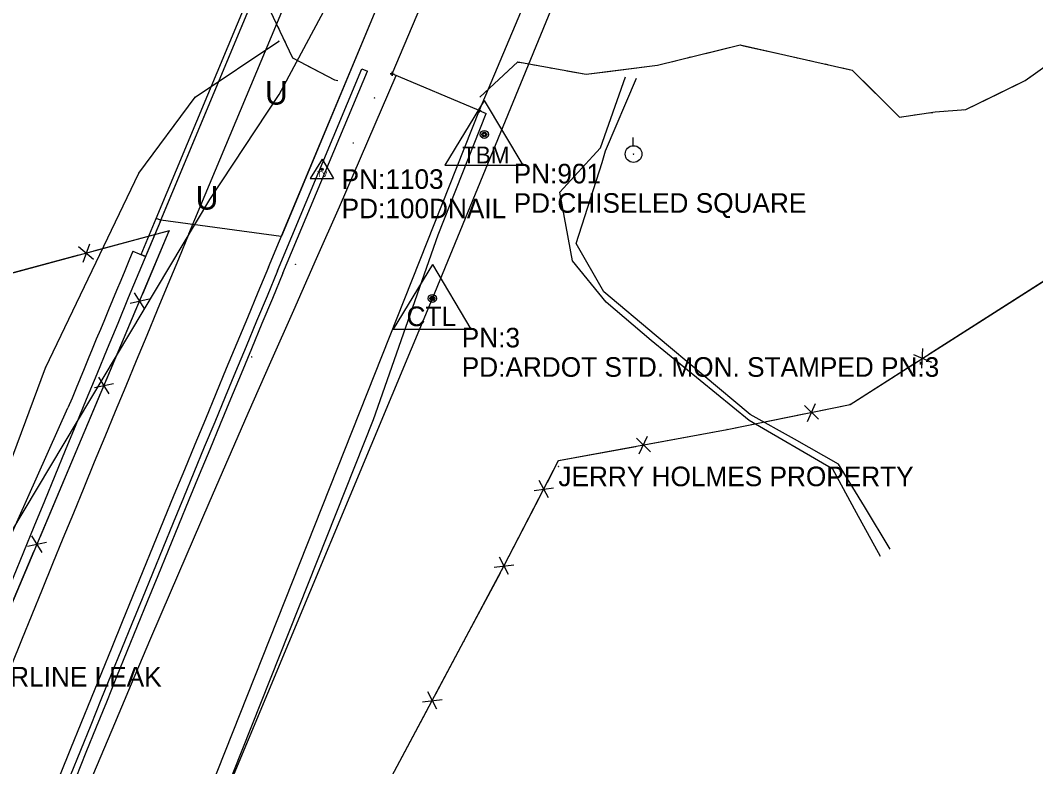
# Model space of a CAD drawing. Extents: x 1282810 to 1284464, y 402460 to 405899.
# Drawn here: x 1283291.6 to 1283550.7, y 403680.6 to 403871.1 of the extents above; entities that cross this region are included whole.
import ezdxf

# ---------------------------------------------------------------- set-up
doc = ezdxf.new("R2010")
doc.units = 0
for name, color, linetype in [('Default', 7, 'Continuous'), ('MOT_Bridge_Stage 2', 7, 'Continuous'), ('MOT_Proposed Road_Stage 2', 7, 'Continuous'), ('MOT_Shld_Stage 2', 7, 'Continuous'), ('MOT_Stage 1_Proposed Road', 7, 'Continuous'), ('MOT_Stage 1_Shld', 7, 'Continuous'), ('MOT_Stage 2_Retaining Wall', 7, 'Continuous'), ('S_BASELINE', 7, 'Continuous'), ('S_BRIDGE', 7, 'Continuous'), ('S_DITCHLINE', 7, 'Continuous'), ('S_EDGE_PAVEMENT', 7, 'Continuous'), ('S_FENCE', 7, 'Continuous'), ('S_MSC_PT_SYM', 7, 'Continuous'), ('S_PRIMARY_CTL', 7, 'Continuous'), ('S_PRIMARY_CTL_ANNOT', 7, 'Continuous'), ('S_RDW_PT_SYM', 7, 'Continuous'), ('S_SECONDARY_CTL', 7, 'Continuous'), ('S_SECONDARY_CTL_ANNOT', 7, 'Continuous'), ('S_STR_PT_SYM', 7, 'Continuous'), ('S_STREAM', 7, 'Continuous'), ('S_SURVEY_TEXT_ANNOT', 7, 'Continuous'), ('S_UNDERGROUND_CABLE', 7, 'Continuous'), ('S_UTILITY_POLE', 7, 'Continuous'), ('S_UTL_PT_SYM', 7, 'Continuous'), ('S_WATER_UTILITIES', 7, 'Continuous')]:
    doc.layers.add(name, color=color, linetype=linetype)

msp = doc.modelspace()

# ---------------------------------------------------------------- linework, layer by layer
at = {"layer": 'MOT_Bridge_Stage 2'}
for p, q in [((1283326.31, 403820.53), (1283390.08, 403973.25)), ((1283327.46, 403820.05), (1283391.24, 403972.77)), ((1283358.34, 403816.13), (1283421.92, 403968.39)), ((1283322.45, 403811.3), (1283326.31, 403820.53)), ((1283327.46, 403820.05), (1283323.61, 403810.82)), ((1283327.46, 403820.05), (1283326.31, 403820.53)), ((1283327.46, 403820.05), (1283326.31, 403820.53)), ((1283358.24, 403815.9), (1283327.46, 403820.05)), ((1283323.61, 403810.82), (1283322.45, 403811.3))]:
    msp.add_line(p, q, dxfattribs=at)
at = {"layer": 'MOT_Proposed Road_Stage 2'}
for p, q in [((1283334.68, 403816.57), (1283508.7, 404233.27)), ((1283354.98, 403808.09), (1283529, 404224.79))]:
    msp.add_line(p, q, dxfattribs=at)
for radius in [11483.16, 11461.16]:
    msp.add_arc((1293930.9, 399391.32), radius, 157.333333, 159.572534, dxfattribs=at)
at = {"layer": 'MOT_Shld_Stage 2'}
for p, q in [((1283327.3, 403819.65), (1283501.32, 404236.35)), ((1283327.3, 403819.65), (1283501.32, 404236.35)), ((1283327.3, 403819.65), (1283501.32, 404236.35)), ((1283327.3, 403819.65), (1283501.32, 404236.35)), ((1283327.3, 403819.65), (1283501.32, 404236.35)), ((1283327.3, 403819.65), (1283501.32, 404236.35)), ((1283320.38, 403812.17), (1283323.61, 403810.82)), ((1283262.75, 403680.57), (1283303.81, 403772.18))]:
    msp.add_line(p, q, dxfattribs=at)
for centre, radius, start, end in [((1293930.9, 399391.32), 11491.16, 157.333333, 159.572534), ((1293930.9, 399391.32), 11491.16, 157.333333, 159.572534), ((1293931.6, 399392.99), 11494.66, 157.390099, 157.605879)]:
    msp.add_arc(centre, radius, start, end, dxfattribs=at)
at = {"layer": 'MOT_Stage 1_Proposed Road'}
msp.add_line((1283408.71, 403848.09), (1283219.41, 403370.59), dxfattribs=at)
at = {"layer": 'MOT_Stage 1_Shld'}
for p in [(1283408.71, 403848.09), (1283398.29, 403816.37)]:
    msp.add_line(p, (1283410.55, 403847.31), dxfattribs=at)
msp.add_lwpolyline([(1283335.29, 403647.86), (1283341.21, 403666.97), (1283381.73, 403769.19), (1283398.29, 403816.37)], dxfattribs=at)
at = {"layer": 'MOT_Stage 2_Retaining Wall'}
for p, q in [((1283357.29, 403807.13), (1283378.82, 403858.69)), ((1283358.67, 403806.55), (1283380.2, 403858.12)), ((1283378.82, 403858.69), (1283380.2, 403858.12))]:
    msp.add_line(p, q, dxfattribs=at)
for radius in [11458.66, 11457.16]:
    msp.add_arc((1293930.9, 399391.32), radius, 157.333333, 159.562079, dxfattribs=at)
at = {"layer": 'S_BASELINE'}
for p, q in [((1283396.79, 403800.11), (1283700.58, 404538.68)), ((1283161.19, 403235.09), (1283396.79, 403800.11))]:
    msp.add_line(p, q, dxfattribs=at)
at = {"layer": 'S_BRIDGE'}
for p, q in [((1283386.52, 403857.44), (1283422.73, 403943.16)), ((1283444.84, 403934.02), (1283408.77, 403848.06)), ((1283408.77, 403848.06), (1283386.52, 403857.44))]:
    msp.add_line(p, q, dxfattribs=at)
at = {"layer": 'S_DITCHLINE'}
for points in [[(1283511.1, 403734.2), (1283505.03, 403745.35), (1283498.95, 403756.51), (1283477.63, 403768.95), (1283465.12, 403779.18), (1283452.62, 403789.41), (1283441.17, 403799.2), (1283432.51, 403809.71), (1283429.32, 403827.22), (1283437.77, 403836.44), (1283439.67, 403838.54), (1283446.03, 403856.66)], [(1283513.65, 403736.12), (1283507.05, 403746.98), (1283500.44, 403757.84), (1283489.17, 403764.16), (1283477.9, 403770.48), (1283465.9, 403780.51), (1283453.89, 403790.55), (1283440.57, 403801.81), (1283433.46, 403814.15), (1283440.11, 403834.82), (1283440.95, 403837.76), (1283448.85, 403856.35)]]:
    msp.add_lwpolyline(points, dxfattribs=at)
at = {"layer": 'S_EDGE_PAVEMENT'}
msp.add_lwpolyline([(1283293.23, 403639.37), (1283302.63, 403661.02), (1283310.16, 403678.33), (1283315.1, 403690.01), (1283320.05, 403701.69), (1283324.99, 403713.37), (1283329.94, 403725.05), (1283339.86, 403747.91), (1283349.79, 403770.78), (1283355.61, 403783.95), (1283361.42, 403797.12), (1283367.24, 403810.3), (1283373.06, 403823.47), (1283380.28, 403840.24), (1283387.51, 403857.01)], dxfattribs=at)
at = {"layer": 'S_FENCE'}
for p, q in [((1283329.66, 403817.36), (1283143.67, 403767.43)), ((1283261.12, 403654.99), (1283329.66, 403817.36)), ((1283309.27, 403814), (1283307.56, 403809.3)), ((1283503.36, 403773.04), (1283570.67, 403815.95)), ((1283310.33, 403810.05), (1283306.5, 403813.26)), ((1283323.44, 403797.34), (1283320.78, 403801.58)), ((1283319.66, 403798.94), (1283324.55, 403799.99)), ((1283519.53, 403785.77), (1283524.14, 403783.85)), ((1283521.73, 403782.32), (1283521.93, 403787.31)), ((1283310.55, 403777.36), (1283315.44, 403778.4)), ((1283314.33, 403775.76), (1283311.67, 403780)), ((1283471.99, 403766.62), (1283503.36, 403773.04)), ((1283491.72, 403772.75), (1283495.35, 403769.31)), ((1283492.54, 403768.73), (1283494.53, 403773.32)), ((1283429.01, 403758.73), (1283471.99, 403766.62)), ((1283449.6, 403760.43), (1283451.68, 403764.97)), ((1283448.86, 403764.46), (1283452.42, 403760.95)), ((1283415.11, 403731.9), (1283429.01, 403758.73)), ((1283422.75, 403751.09), (1283427.7, 403751.75)), ((1283426.39, 403749.21), (1283424.07, 403753.64)), ((1283297.22, 403735.24), (1283294.56, 403739.47)), ((1283293.44, 403736.83), (1283298.33, 403737.88)), ((1283416.21, 403729.6), (1283413.92, 403734.03)), ((1283404.86, 403712.59), (1283415.11, 403731.9)), ((1283412.59, 403731.52), (1283417.54, 403732.11)), ((1283386.47, 403678.17), (1283404.86, 403712.59)), ((1283394.29, 403697.15), (1283399.25, 403697.73)), ((1283397.9, 403695.22), (1283395.63, 403699.66))]:
    msp.add_line(p, q, dxfattribs=at)
for points in [[(1283329.66, 403817.36), (1283310.35, 403812.17)], [(1283322.89, 403801.3), (1283329.66, 403817.36)], [(1283306.48, 403811.13), (1283267.85, 403800.76)], [(1283523.51, 403785.88), (1283557.1, 403807.3)], [(1283313.55, 403779.2), (1283321.33, 403797.62)], [(1283503.36, 403773.04), (1283520.15, 403783.74)], [(1283296.67, 403739.2), (1283312.22, 403776.04)], [(1283495.49, 403771.43), (1283503.36, 403773.04)], [(1283471.99, 403766.62), (1283491.57, 403770.63)], [(1283452.6, 403763.06), (1283471.99, 403766.62)], [(1283429.01, 403758.73), (1283448.67, 403762.34)], [(1283426.15, 403753.2), (1283429.01, 403758.73)], [(1283415.11, 403731.9), (1283424.31, 403749.65)], [(1283287.34, 403717.1), (1283295.11, 403735.52)], [(1283404.86, 403712.59), (1283414.14, 403730.07)], [(1283397.71, 403699.19), (1283404.86, 403712.59)], [(1283386.47, 403678.17), (1283395.83, 403695.69)]]:
    msp.add_lwpolyline(points, dxfattribs=at)
at = {"layer": 'S_MSC_PT_SYM'}
for points in [[(1283329.66, 403817.36), (1283329.66, 403817.41), (1283329.66, 403817.36), (1283329.61, 403817.36), (1283329.66, 403817.36), (1283329.66, 403817.31), (1283329.66, 403817.36), (1283329.71, 403817.36)], [(1283503.36, 403773.04), (1283503.36, 403773.09), (1283503.36, 403773.04), (1283503.31, 403773.04), (1283503.36, 403773.04), (1283503.36, 403772.99), (1283503.36, 403773.04), (1283503.41, 403773.04)], [(1283471.99, 403766.62), (1283471.99, 403766.67), (1283471.99, 403766.62), (1283471.94, 403766.62), (1283471.99, 403766.62), (1283471.99, 403766.57), (1283471.99, 403766.62), (1283472.04, 403766.62)], [(1283428.95, 403757.18), (1283428.95, 403757.23), (1283428.95, 403757.18), (1283428.9, 403757.18), (1283428.95, 403757.18), (1283428.95, 403757.13), (1283428.95, 403757.18), (1283429, 403757.18)], [(1283429.01, 403758.73), (1283429.01, 403758.78), (1283429.01, 403758.73), (1283428.96, 403758.73), (1283429.01, 403758.73), (1283429.01, 403758.68), (1283429.01, 403758.73), (1283429.06, 403758.73)], [(1283415.11, 403731.9), (1283415.11, 403731.95), (1283415.11, 403731.9), (1283415.06, 403731.9), (1283415.11, 403731.9), (1283415.11, 403731.85), (1283415.11, 403731.9), (1283415.16, 403731.9)], [(1283404.86, 403712.59), (1283404.86, 403712.64), (1283404.86, 403712.59), (1283404.81, 403712.59), (1283404.86, 403712.59), (1283404.86, 403712.54), (1283404.86, 403712.59), (1283404.91, 403712.59)]]:
    msp.add_lwpolyline(points, dxfattribs=at)
at = {"layer": 'S_PRIMARY_CTL'}
for p, q in [((1283410.04, 403850.68), (1283400, 403834.16)), ((1283410.04, 403850.68), (1283419.86, 403834.16)), ((1283400, 403834.16), (1283419.86, 403834.16)), ((1283396.79, 403808.81), (1283386.75, 403792.3)), ((1283396.79, 403808.81), (1283406.61, 403792.3)), ((1283386.75, 403792.3), (1283406.61, 403792.3))]:
    msp.add_line(p, q, dxfattribs=at)
for centre, radius in [((1283410.04, 403841.98), 1.04), ((1283410.04, 403841.98), 0.609), ((1283410.04, 403841.98), 0.344), ((1283396.79, 403800.11), 1.04), ((1283396.79, 403800.11), 0.609), ((1283396.79, 403800.11), 0.344)]:
    msp.add_circle(centre, radius, dxfattribs=at)
at = {"layer": 'S_RDW_PT_SYM'}
for points in [[(1283382, 403851.28), (1283382, 403851.33), (1283382, 403851.28), (1283381.95, 403851.28), (1283382, 403851.28), (1283382, 403851.23), (1283382, 403851.28), (1283382.05, 403851.28)], [(1283376.59, 403839.82), (1283376.59, 403839.87), (1283376.59, 403839.82), (1283376.54, 403839.82), (1283376.59, 403839.82), (1283376.59, 403839.77), (1283376.59, 403839.82), (1283376.64, 403839.82)], [(1283361.89, 403808.85), (1283361.89, 403808.9), (1283361.89, 403808.85), (1283361.83, 403808.85), (1283361.89, 403808.85), (1283361.89, 403808.8), (1283361.89, 403808.85), (1283361.94, 403808.85)], [(1283350.71, 403785.18), (1283350.71, 403785.23), (1283350.71, 403785.18), (1283350.66, 403785.18), (1283350.71, 403785.18), (1283350.71, 403785.13), (1283350.71, 403785.18), (1283350.76, 403785.18)]]:
    msp.add_lwpolyline(points, dxfattribs=at)
at = {"layer": 'S_SECONDARY_CTL'}
for p, q in [((1283368.64, 403835.69), (1283365.63, 403830.74)), ((1283368.64, 403835.69), (1283371.58, 403830.74)), ((1283365.63, 403830.74), (1283371.58, 403830.74))]:
    msp.add_line(p, q, dxfattribs=at)
for radius in [0.311, 0.183, 0.103]:
    msp.add_circle((1283368.64, 403833.08), radius, dxfattribs=at)
at = {"layer": 'S_STR_PT_SYM'}
for points in [[(1283386.52, 403857.44), (1283386.52, 403857.94), (1283386.52, 403857.44), (1283386.02, 403857.44), (1283386.52, 403857.44), (1283386.52, 403856.94), (1283386.52, 403857.44), (1283387.02, 403857.44)], [(1283408.77, 403848.06), (1283408.77, 403848.56), (1283408.77, 403848.06), (1283408.27, 403848.06), (1283408.77, 403848.06), (1283408.77, 403847.56), (1283408.77, 403848.06), (1283409.27, 403848.06)]]:
    msp.add_lwpolyline(points, dxfattribs=at)
at = {"layer": 'S_STREAM'}
for points in [[(1283155.14, 403780.67), (1283168.76, 403789.1), (1283182.38, 403797.52), (1283197.41, 403805.48), (1283208.78, 403811.07), (1283220.16, 403816.66), (1283233.26, 403832.25), (1283245.23, 403846.1), (1283257.2, 403859.95), (1283270.89, 403870.02), (1283284.59, 403880.1), (1283303.96, 403895.89), (1283313.81, 403885.53), (1283332.16, 403884.74), (1283350.5, 403883.96), (1283361.12, 403861.52), (1283371.83, 403855.95), (1283372.66, 403855.71)], [(1283357.28, 403869.64), (1283357.58, 403869)], [(1283408.91, 403851.46), (1283418.58, 403860.48), (1283436.04, 403857.36), (1283454.25, 403859.69), (1283475.29, 403864.82), (1283489.58, 403861.62), (1283503.87, 403858.42), (1283516, 403846.4), (1283525.06, 403847.71), (1283532.94, 403848.33), (1283548.02, 403855.75), (1283566.59, 403868.95)], [(1283358.94, 403866.13), (1283359.24, 403865.5)], [(1283466.45, 403862.67), (1283475.29, 403864.82), (1283476.16, 403864.63)], [(1283476.17, 403864.63), (1283485.91, 403862.44)], [(1283360.6, 403862.62), (1283360.9, 403861.99)], [(1283458.11, 403860.63), (1283458.81, 403860.8)], [(1283461.99, 403861.57), (1283462.69, 403861.75)], [(1283489.2, 403861.7), (1283489.58, 403861.62), (1283489.91, 403861.55)], [(1283493.1, 403860.83), (1283493.81, 403860.67)], [(1283363.99, 403860.02), (1283371.83, 403855.95), (1283372.66, 403855.71)], [(1283408.91, 403851.46), (1283416.21, 403858.27)], [(1283418.71, 403860.46), (1283419.42, 403860.33)], [(1283422.64, 403859.76), (1283423.35, 403859.63)], [(1283426.57, 403859.05), (1283427.28, 403858.93)], [(1283431.1, 403858.25), (1283436.04, 403857.36), (1283440.97, 403857.99)], [(1283440.98, 403857.99), (1283450.88, 403859.26)], [(1283454.23, 403859.68), (1283454.25, 403859.69), (1283454.93, 403859.85)], [(1283497, 403859.96), (1283497.7, 403859.8)], [(1283501.48, 403858.95), (1283503.87, 403858.42), (1283509.23, 403853.11)], [(1283541.33, 403852.46), (1283548.02, 403855.75), (1283550.09, 403857.22)], [(1283509.23, 403853.1), (1283516, 403846.4), (1283516.46, 403846.47)], [(1283532.3, 403848.28), (1283532.94, 403848.33), (1283541.33, 403852.46)], [(1283523.75, 403847.52), (1283524.46, 403847.62)], [(1283527.72, 403847.92), (1283528.44, 403847.98)], [(1283519.79, 403846.95), (1283520.51, 403847.05)]]:
    msp.add_lwpolyline(points, dxfattribs=at)
at = {"layer": 'S_UNDERGROUND_CABLE'}
for p, q in [((1283357.72, 403852.14), (1283384.5, 403902.46)), ((1283340.02, 403825.33), (1283357.72, 403852.14)), ((1283240.13, 403658.24), (1283340.02, 403825.33))]:
    msp.add_line(p, q, dxfattribs=at)
at = {"layer": 'S_UTILITY_POLE'}
msp.add_line((1283448, 403839.12), (1283448, 403841.22), dxfattribs=at)
msp.add_circle((1283448.12, 403836.98), 2.13, dxfattribs=at)
at = {"layer": 'S_UTL_PT_SYM'}
for points in [[(1283357.61, 403865.76), (1283357.61, 403865.81), (1283357.61, 403865.76), (1283357.56, 403865.76), (1283357.61, 403865.76), (1283357.61, 403865.71), (1283357.61, 403865.76), (1283357.66, 403865.76)], [(1283336.24, 403851.48), (1283336.24, 403851.53), (1283336.24, 403851.48), (1283336.19, 403851.48), (1283336.24, 403851.48), (1283336.24, 403851.43), (1283336.24, 403851.48), (1283336.29, 403851.48)], [(1283448.12, 403836.98), (1283448.12, 403837.03), (1283448.12, 403836.98), (1283448.07, 403836.98), (1283448.12, 403836.98), (1283448.12, 403836.93), (1283448.12, 403836.98), (1283448.17, 403836.98)], [(1283321.89, 403832.11), (1283321.89, 403832.16), (1283321.89, 403832.11), (1283321.84, 403832.11), (1283321.89, 403832.11), (1283321.89, 403832.06), (1283321.89, 403832.11), (1283321.94, 403832.11)], [(1283298.04, 403782.43), (1283298.04, 403782.48), (1283298.04, 403782.43), (1283297.99, 403782.43), (1283298.04, 403782.43), (1283298.04, 403782.38), (1283298.04, 403782.43), (1283298.09, 403782.43)]]:
    msp.add_lwpolyline(points, dxfattribs=at)
at = {"layer": 'S_WATER_UTILITIES'}
for p, q in [((1283336.24, 403851.48), (1283357.61, 403865.76)), ((1283321.89, 403832.11), (1283336.24, 403851.48)), ((1283298.04, 403782.43), (1283321.89, 403832.11)), ((1283274.53, 403719.02), (1283298.04, 403782.43))]:
    msp.add_line(p, q, dxfattribs=at)

# ---------------------------------------------------------------- texts
at = {"layer": 'Default'}
for p in [(1283354.09, 403849.59), (1283336.39, 403822.79)]:
    msp.add_text('U', height=6, rotation=360, dxfattribs=at).set_placement(p)
at = {"layer": 'S_PRIMARY_CTL'}
for s, height, p in [('TBM', 4.287, (1283404.38, 403834.59)), ('CTL', 5, (1283390.2, 403793.04))]:
    msp.add_text(s, height=height, rotation=360, dxfattribs=at).set_placement(p)
at = {"layer": 'S_PRIMARY_CTL_ANNOT'}
for s, p in [('PN:901', (1283417.54, 403829.48)), ('PD:CHISELED SQUARE', (1283417.54, 403821.98)), ('PN:3', (1283404.29, 403787.61)), ('PD:ARDOT STD. MON. STAMPED PN:3', (1283404.29, 403780.11))]:
    msp.add_text(s, height=5, dxfattribs=at).set_placement(p)
at = {"layer": 'S_SECONDARY_CTL'}
msp.add_text('TV', height=1.5, rotation=360, dxfattribs=at).set_placement((1283367.43, 403831.07))
at = {"layer": 'S_SECONDARY_CTL_ANNOT'}
for s, p in [('PN:1103', (1283373.64, 403828.08)), ('PD:100DNAIL', (1283373.64, 403820.58))]:
    msp.add_text(s, height=5, dxfattribs=at).set_placement(p)
at = {"layer": 'S_SURVEY_TEXT_ANNOT'}
for s, p in [('JERRY HOLMES PROPERTY', (1283428.95, 403752.18)), ('WATERLINE LEAK', (1283269.74, 403701.04))]:
    msp.add_text(s, height=5, dxfattribs=at).set_placement(p)

doc.saveas('drawing.dxf')
